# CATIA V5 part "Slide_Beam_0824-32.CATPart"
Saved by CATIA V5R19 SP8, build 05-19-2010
Part number: Slide Beam 0824-32
Definition: Slide Beam 0824-32
Nomenclature: 60006
Material "Aluminium": density 2710 kg/m3, Young's modulus 7e+10 Pa, Poisson ratio 0.346, thermal expansion 2.36e-05 1/K
Bounding box of the stored display mesh (mm): x -16 to 16, y -12 to 12, z -4 to 4
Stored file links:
  D:\Documents\1_Travail\1 - ac-limoges.fr\ac-limoges.fr\Emmanuel Maynard - STI2D_Turgot\1 - IT-I2D\Activités_IT_Première\IT_3_Abris_bus\Maquettes numériques\Abribus_eleve\Slide_Beam_0824-32.CATPart
  D:\Documents\1_Travail\1 - ITEC_Turgot\6 -  Ressources ITEC\Ressources Techniques\0-Maquettes numériques_Composants\Makeblock\Catalogue_Makeblock_catia.xlsx
  D:\Documents\1_Travail\2- 2I2D\6 -  Ressources ITEC\Ressources Techniques\0-Maquettes numériques_Composants\Catalogue_Makeblock\Catalog_Makeblock\01_Profilés\Table_Beam0824.xls
  C:\Program Files\Dassault Systemes\B19\win_b64\startup\materials\French\Catalog.CATMaterial
  D:\Documents\1_Travail\2- 2I2D\6 -  Ressources ITEC\Ressources Techniques\0-Maquettes numériques_Composants\Catalogue_Makeblock\Catalog_Makeblock\01_Profilés\Table_Beam0824.txt
  D:\Documents\1_Travail\2- 2I2D\6 -  Ressources ITEC\Ressources Techniques\0-Maquettes numériques_Composants\Catalogue_Makeblock\Catalog_Makeblock\01_Profilés\Table_Slide_Beam0824.txt
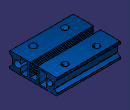
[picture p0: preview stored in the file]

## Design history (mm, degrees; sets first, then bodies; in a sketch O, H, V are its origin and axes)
Parameters
  Nb_Trous = 2
  Longueur = 32 mm
  Nb_Repet = 3
  Repet_Trou = false
  `Désignation` = "Slide Beam 0824-32"
  `Référence` = "60006"
AxisSystem1: origin (0, 0, 0), X (1, 0, 0), Y (0, 1, 0), Z (0, 0, 1)
Body1 (main body), material "Aluminium"
  Sketch1 on YZ plane of AxisSystem1, origin (0, 0, 0), H (0, 1, 0), V (0, 0, 1)
    line L1 (12, 4) -> (12, 2.9)
    line L2 (12, -4) -> (-12, -4)
    line L3 (-12, -4) -> (-12, -2.9)
    line L4 (-12, 4) -> (-1.6212, 4)
    point P1 (12, 4)
    point P2 (12, -4)
    point P5 (0, 1.1525)
    line L5 (1.6212, 3.65) -> (1.6212, 3.4386)
    line L6 (1.6212, -2.6) -> (-1.6212, -2.6)
    line L7 (-1.6212, -2.6) -> (-1.6212, -2.2192)
    line L8 (1.9496, 4) -> (12, 4)
    point P9 (-2.0758, 3.6427)
    line L9 (-2, 3.5989) -> (-1.6212, 3.3802)
    axis line L10 (-2.0758, 5.0021) -> (-2.0758, -2.577)
    reference intersected line E1 through (0, 0) direction (0, 1) from ZX plane of AxisSystem1
    arc A1 centre (-1.9705, 3.65) radius 0.059 from (-2, 3.7011) to (-2, 3.5989) ccw
    point P12 (-2, 3.7011)
    point P14 (-1.9705, 3.65)
    reference intersected line E2 through (0, 0) direction (0, 1) from ZX plane of AxisSystem1
    line L11 (-2, 3.7011) -> (-1.6212, 3.9198)
    point P16 (-1.6212, 3.9198)
    point P18 (-2, 3.0012)
    line L12 (-2, 3.0012) -> (-1.6212, 3.2199)
    point P20 (-1.9705, 2.9501)
    arc A2 centre (-1.9705, 2.9501) radius 0.059 from (-2, 3.0012) to (-2, 2.899) ccw
    line L13 (-2, 2.899) -> (-1.6212, 2.6803)
    point P23 (-2, 2.3013)
    line L14 (-2, 2.3013) -> (-1.6212, 2.52)
    point P25 (-1.9705, 2.2502)
    arc A3 centre (-1.9705, 2.2502) radius 0.059 from (-2, 2.3013) to (-2, 2.1991) ccw
    line L15 (-2, 2.1991) -> (-1.6212, 1.9803)
    point P28 (-2, 1.6013)
    line L16 (-2, 1.6013) -> (-1.6212, 1.8201)
    point P30 (-1.9705, 1.5502)
    arc A4 centre (-1.9705, 1.5502) radius 0.059 from (-2, 1.6013) to (-2, 1.4991) ccw
    line L17 (-2, 1.4991) -> (-1.6212, 1.2804)
    point P33 (-2, 0.9014)
    line L18 (-2, 0.9014) -> (-1.6212, 1.1201)
    point P35 (-1.9705, 0.8503)
    arc A5 centre (-1.9705, 0.8503) radius 0.059 from (-2, 0.9014) to (-2, 0.7992) ccw
    line L19 (-2, 0.7992) -> (-1.6212, 0.5805)
    point P38 (-2, 0.2015)
    line L20 (-2, 0.2015) -> (-1.6212, 0.4202)
    point P40 (-1.9705, 0.1504)
    arc A6 centre (-1.9705, 0.1504) radius 0.059 from (-2, 0.2015) to (-2, 0.0993) ccw
    line L21 (-2, 0.0993) -> (-1.6212, -0.1194)
    point P43 (-2, -0.4984)
    line L22 (-2, -0.4984) -> (-1.6212, -0.2797)
    point P45 (-1.9705, -0.5495)
    arc A7 centre (-1.9705, -0.5495) radius 0.059 from (-2, -0.4984) to (-2, -0.6006) ccw
    line L23 (-2, -0.6006) -> (-1.6212, -0.8193)
    point P48 (-2, -1.1983)
    line L24 (-2, -1.1983) -> (-1.6212, -0.9796)
    point P50 (-1.9705, -1.2494)
    arc A8 centre (-1.9705, -1.2494) radius 0.059 from (-2, -1.1983) to (-2, -1.3005) ccw
    line L25 (-2, -1.3005) -> (-1.6212, -1.5193)
    point P53 (-2, -1.8983)
    line L26 (-2, -1.8983) -> (-1.6212, -1.6795)
    point P55 (-1.9705, -1.9494)
    arc A9 centre (-1.9705, -1.9494) radius 0.059 from (-2, -1.8983) to (-2, -2.0005) ccw
    line L27 (-2, -2.0005) -> (-1.6212, -2.2192)
    point P57 (-2, -2.5982)
    point P58 (-2, -3.2981)
    line L28 (-1.6212, 3.9198) -> (-1.6212, 4)
    line L29 (-1.6212, 3.2199) -> (-1.6212, 3.3802)
    line L30 (-1.6212, 2.52) -> (-1.6212, 2.6803)
    line L31 (-1.6212, 1.8201) -> (-1.6212, 1.9803)
    line L32 (-1.6212, 1.1201) -> (-1.6212, 1.2804)
    line L33 (-1.6212, 0.4202) -> (-1.6212, 0.5805)
    line L34 (-1.6212, -0.2797) -> (-1.6212, -0.1194)
    line L35 (-1.6212, -0.9796) -> (-1.6212, -0.8193)
    line L36 (-1.6212, -1.6795) -> (-1.6212, -1.5193)
    line L37 (2, 3.9709) -> (1.9496, 4)
    arc A10 centre (1.9705, 3.9198) radius 0.059 from (2, 3.9709) to (2, 3.8687) cw
    point P64 (1.6212, 3.65)
    line L38 (2, 3.8687) -> (1.6212, 3.65)
    line L39 (2, 3.2199) -> (1.6212, 3.4386)
    arc A11 centre (1.9705, 3.1688) radius 0.059 from (2, 3.2199) to (2, 3.1177) cw
    line L40 (2, 3.1177) -> (1.6212, 2.899)
    line L41 (2, 2.4689) -> (1.6212, 2.6876)
    arc A12 centre (1.9705, 2.4178) radius 0.059 from (2, 2.4689) to (2, 2.3667) cw
    line L42 (2, 2.3667) -> (1.6212, 2.148)
    line L43 (2, 1.7179) -> (1.6212, 1.9366)
    arc A13 centre (1.9705, 1.6668) radius 0.059 from (2, 1.7179) to (2, 1.6157) cw
    line L44 (2, 1.6157) -> (1.6212, 1.397)
    line L45 (2, 0.9669) -> (1.6212, 1.1856)
    arc A14 centre (1.9705, 0.9158) radius 0.059 from (2, 0.9669) to (2, 0.8647) cw
    line L46 (2, 0.8647) -> (1.6212, 0.6459)
    line L47 (2, 0.2158) -> (1.6212, 0.4346)
    arc A15 centre (1.9705, 0.1647) radius 0.059 from (2, 0.2158) to (2, 0.1136) cw
    line L48 (2, 0.1136) -> (1.6212, -0.1051)
    line L49 (2, -0.5352) -> (1.6212, -0.3165)
    arc A16 centre (1.9705, -0.5863) radius 0.059 from (2, -0.5352) to (2, -0.6374) cw
    line L50 (2, -0.6374) -> (1.6212, -0.8561)
    line L51 (2, -1.2862) -> (1.6212, -1.0675)
    arc A17 centre (1.9705, -1.3373) radius 0.059 from (2, -1.2862) to (2, -1.3884) cw
    line L52 (2, -1.3884) -> (1.6212, -1.6071)
    line L53 (2, -2.0372) -> (1.6212, -1.8185)
    arc A18 centre (1.9705, -2.0883) radius 0.059 from (2, -2.0372) to (2, -2.1394) cw
    line L54 (2, -2.1394) -> (1.6212, -2.3581)
    line L55 (1.6212, -2.3581) -> (1.6212, -2.6)
    line L56 (1.6212, -1.6071) -> (1.6212, -1.8185)
    line L57 (1.6212, -0.8561) -> (1.6212, -1.0675)
    line L58 (1.6212, -0.1051) -> (1.6212, -0.3165)
    line L59 (1.6212, 0.6459) -> (1.6212, 0.4346)
    line L60 (1.6212, 1.397) -> (1.6212, 1.1856)
    line L61 (1.6212, 2.148) -> (1.6212, 1.9366)
    line L62 (1.6212, 2.899) -> (1.6212, 2.6876)
    point P106 (12, 2.9)
    line L63 (12, 2.9) -> (10.6, 1.5)
    point P107 (10.6, 1.5)
    line L64 (10.6, 1.5) -> (10.6, -1.5)
    point P108 (10.6, -1.5)
    line L65 (10.6, -1.5) -> (12, -2.9)
    point P109 (12, -2.9)
    line L66 (12, -2.9) -> (12, -4)
    arc A19 centre (8, 0) radius 1.65 from (6.5, -0.6874) to (6.5, 0.6874) ccw
    point P110 (8, 0)
    point P111 (7.521, -1.579)
    reference intersected line E4 through (0, 0) direction (0, 1) from ZX plane of AxisSystem1
    point P112 (4.7206, 0)
    line L67 (6.5, 2.95) -> (6.5, 0.6874)
    line L68 (6.2, -3.25) -> (3.2412, -3.25)
    line L69 (2.9412, -2.95) -> (2.9412, 2.95)
    line L70 (3.2412, 3.25) -> (6.2, 3.25)
    point P113 (6.3398, -1.5387)
    point P114 (6.5, -0.9716)
    point P115 (6.5, 0.6874)
    point P116 (6.5, 0.6874)
    line L71 (6.5, -0.6874) -> (6.5, -2.95)
    arc A20 centre (3.2412, 2.95) radius 0.3 from (2.9412, 2.95) to (3.2412, 3.25) cw
    point P117 (2.9412, 2.95)
    point P118 (3.2412, 3.25)
    arc A21 centre (6.2, 2.95) radius 0.3 from (6.5, 2.95) to (6.2, 3.25) ccw
    point P120 (6.5, 2.95)
    point P121 (6.2, 3.25)
    arc A22 centre (6.2, -2.95) radius 0.3 from (6.2, -3.25) to (6.5, -2.95) ccw
    point P123 (6.2, -3.25)
    point P124 (6.5, -2.95)
    arc A23 centre (3.2412, -2.95) radius 0.3 from (3.2412, -3.25) to (2.9412, -2.95) cw
    point P126 (3.2412, -3.25)
    point P127 (2.9412, -2.95)
    reference projected line E5 through (0, 0) direction (0, 1) from edge [ZX plane of AxisSystem1 | YZ plane of AxisSystem1]
    point P131 (-12, 4)
    point P132 (-12, -4)
    point P133 (-12, 2.9)
    point P134 (-10.6, 1.5)
    point P135 (-10.6, -1.5)
    point P136 (-12, -2.9)
    point P138 (-7.521, -1.579)
    point P139 (-4.7206, 0)
    point P140 (-6.3398, -1.5387)
    point P141 (-6.5, 0.6874)
    point P142 (-6.5, 0.6874)
    point P143 (-2.9412, 2.95)
    point P144 (-3.2412, 3.25)
    point P146 (-6.5, 2.95)
    point P147 (-6.2, 3.25)
    point P149 (-6.2, -3.25)
    point P150 (-6.5, -2.95)
    point P152 (-3.2412, -3.25)
    point P153 (-2.9412, -2.95)
    line L72 (-12, 2.9) -> (-10.6, 1.5)
    line L73 (-10.6, 1.5) -> (-10.6, -1.5)
    line L74 (-10.6, -1.5) -> (-12, -2.9)
    arc A24 centre (-8, 0) radius 1.65 from (-6.5, -0.6874) to (-6.5, 0.6874) cw
    line L75 (-6.5, 2.95) -> (-6.5, 0.6874)
    line L76 (-6.2, -3.25) -> (-3.2412, -3.25)
    line L77 (-2.9412, -2.95) -> (-2.9412, 2.95)
    line L78 (-3.2412, 3.25) -> (-6.2, 3.25)
    line L79 (-6.5, -0.6874) -> (-6.5, -2.95)
    arc A25 centre (-3.2412, 2.95) radius 0.3 from (-2.9412, 2.95) to (-3.2412, 3.25) ccw
    arc A26 centre (-6.2, 2.95) radius 0.3 from (-6.5, 2.95) to (-6.2, 3.25) cw
    arc A27 centre (-6.2, -2.95) radius 0.3 from (-6.2, -3.25) to (-6.5, -2.95) cw
    arc A28 centre (-3.2412, -2.95) radius 0.3 from (-3.2412, -3.25) to (-2.9412, -2.95) ccw
    line L80 (-12, 2.9) -> (-12, 4)
    distance L3 L1 = 24
    distance L2 L4 = 8
    distance L7 L5 = 3.2423
    distance L4 L6 = 6.6
    distance L10 E1 = 2.0758
    distance P12 E2 = 2
    distance P14 L4 = 0.35
    angle L11 L9 = 60
    angle L11 L10 = 60
    angle L12 L13 = 60
    distance P18 E2 = 2 (reference)
    distance P20 L4 = 1.0499 (reference)
    angle L12 L10 = 60 (reference)
    angle L14 L15 = 60
    distance P25 L4 = 1.7498 (reference)
    distance P23 E2 = 2 (reference)
    angle L14 L10 = 60 (reference)
    angle L16 L17 = 60
    distance P28 E2 = 2 (reference)
    distance P30 L4 = 2.4498 (reference)
    angle L16 L10 = 60 (reference)
    angle L18 L19 = 60
    distance P33 E2 = 2 (reference)
    distance P35 L4 = 3.1497 (reference)
    angle L18 L10 = 60 (reference)
    angle L20 L21 = 60
    distance P40 L4 = 3.8496 (reference)
    distance P38 E2 = 2 (reference)
    angle L20 L10 = 60 (reference)
    angle L22 L23 = 60
    distance P43 E2 = 2 (reference)
    distance P45 L4 = 4.5495 (reference)
    angle L22 L10 = 60 (reference)
    angle L24 L25 = 60
    distance P48 E2 = 2 (reference)
    distance P50 L4 = 5.2494 (reference)
    angle L24 L10 = 60 (reference)
    angle L26 L27 = 60
    distance P55 L4 = 5.9494 (reference)
    distance P53 E2 = 2 (reference)
    angle L26 L10 = 60 (reference)
    distance P57 E2 = 2 (reference)
    distance P58 E2 = 2 (reference)
    distance L64 L1 = 1.4
    angle L65 L2 = 45
    distance P110 E4 = 8
    radius A19 = 1.65
    distance L8 L70 = 0.75
    distance L69 P64 = 1.32
    radius A20 = 0.3
    radius A21 = 0.3
    radius A22 = 0.3
    radius A23 = 0.3
    distance L67 P110 = 1.5
    length L64 = 3
    distance P108 P110 V = 1.5
    vertical: L1 V, L3 V, L5 V, L7 V, L10 V, L28 V, L29 V, L30 V, L31 V, L32 V, L33 V, L34 V, L35 V, L36 V, L55 V, L56 V, L57 V, L58 V, L59 V, L60 V, L61 V, L62 V, L64 V, L66 V, L67 V, L69 V, L71 V, L80 V
    horizontal: L2 H, L4 H, L6 H, L8 H, L68 H, L70 H
    equidistance: L1 L3 O, L2 L4 O, L5 L7 P5, L67 L69 P112, L68 L70 P112
    coincidence: P5 V, L4 L8, P9 L10, L9 P9, L7 P16, L7 L28, L7 L29, L7 L30, L7 L31, L7 L32, L7 L33, L7 L34, L7 L35, L7 L36, L5 L55, L5 L56, L5 L57, L5 L58, L5 L59, L5 L60, L5 L61, L5 L62, P109 L1, L1 L66, P110 H, A19 P111, P111 L63, P112 H, L67 P114, L67 L71, L3 L80, P116 P115, P114 L71
    tangency: A1 L9, L11 A1, A2 L13, L12 A2, A3 L15, L14 A3, A4 L17, L16 A4, L18 A5, A5 L19, A6 L21, L20 A6, A7 L23, L22 A7, L24 A8, A8 L25, A9 L27, L26 A9, A20 L69, A20 L70, A21 L67, A21 L70, A22 L68, A22 L71, A23 L68, A23 L69
    perpendicularity: L63 L65
    symmetry: P1 P131 E5, P2 P132 E5, P106 P133 E5, P107 P134 E5, P108 P135 E5, P109 P136 E5, P111 P138 E5, P112 P139 E5, P113 P140 E5, P115 P141 E5, P116 P142 E5, P117 P143 E5, P118 P144 E5, P120 P146 E5, P121 P147 E5, P123 P149 E5, P124 P150 E5, P126 P152 E5, P127 P153 E5, L63 L72 E5, L64 L73 E5, L65 L74 E5, A19 A24 E5, L67 L75 E5, L68 L76 E5, L69 L77 E5, L70 L78 E5, L71 L79 E5, A20 A25 E5, A21 A26 E5, A22 A27 E5, A23 A28 E5
  Pad1: profile Sketch1, direction (1, 0, 0), length 16 {= Longueur /2}, mirrored extent
  Fillet1: radius 0.2, on edge [face of Pad1 from Sketch1.L8 | face of Pad1 from Sketch1.L1]; edge [face of Pad1 from Sketch1.L1 | face of Pad1 from Sketch1.L63]; edge [face of Pad1 from Sketch1.L64 | face of Pad1 from Sketch1.L65]; edge [face of Pad1 from Sketch1.L63 | face of Pad1 from Sketch1.L64]; edge [face of Pad1 from Sketch1.L65 | face of Pad1 from Sketch1.L66]; edge [face of Pad1 from Sketch1.L66 | face of Pad1 from Sketch1.L2]; edge [face of Pad1 from Sketch1.L80 | face of Pad1 from Sketch1.L4]; edge [face of Pad1 from Sketch1.L72 | face of Pad1 from Sketch1.L80]; edge [face of Pad1 from Sketch1.L73 | face of Pad1 from Sketch1.L72]; edge [face of Pad1 from Sketch1.L74 | face of Pad1 from Sketch1.L73]; edge [face of Pad1 from Sketch1.L3 | face of Pad1 from Sketch1.L74]; edge [face of Pad1 from Sketch1.L2 | face of Pad1 from Sketch1.L3]
  Sketch2 on face of Pad1 from Sketch1.L8, origin (0, 0, 4), H (1, 0, 0), V (0, 1, 0)
    circle A1 centre (8, 8) radius 1.5641
    point P1 (8, 8)
    circle A2 centre (8, -8) radius 1.7249
    point P2 (8, -8)
    reference intersected line E1 through (16, 0) direction (0, 1) from end face of Pad1
    reference intersected line E2 through (16, 0) direction (0, 1) from end face of Pad1
    reference projected line E3 through (0, 8) direction (1, 0) from axis of face of Pad1 from Sketch1.A19
    reference projected line E4 through (0, -8) direction (1, 0) from axis of face of Pad1 from Sketch1.A24
    distance P1 E1 = 8
    distance P2 E2 = 8
    coincidence: P1 E3, P2 E4
  Pocket1: profile Sketch2, direction (0, 0, -1), through (limit type 3)
  RectPattern1: of Pocket1, direction 1 instances 2 {= Nb_Trous}, spacing 16, along edge [face of Pad1 from Sketch1.L37 | face of Pad1 from Sketch1.L8] reversed
  RectPattern2: of RectPattern1, direction 1 instances 3 {= Nb_Repet}, spacing 0 {= (Longueur/2) -(16mm*(Nb_Trous /2))}, along edge [face of Pad1 from Sketch1.L8 | face of Fillet1] reversed, deactivated
Relations
  RectPattern2.Activity = Repet_Trou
